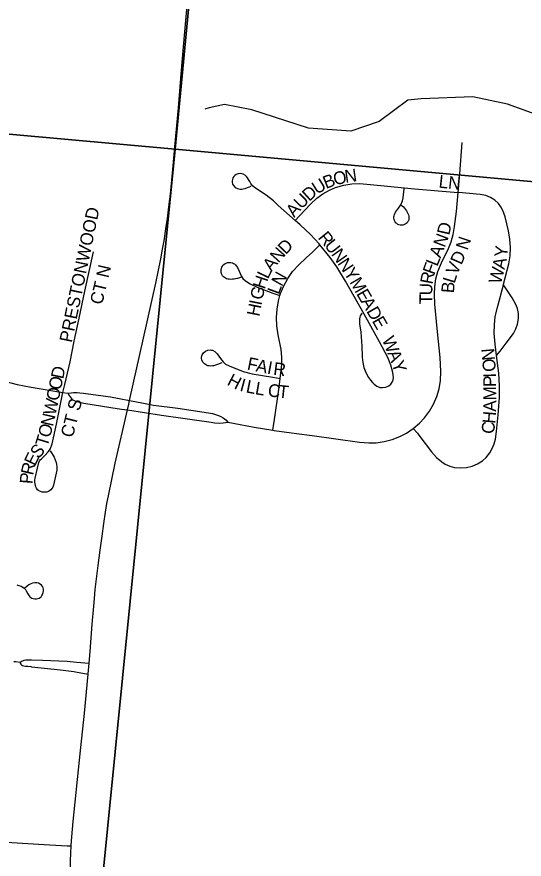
# Model space of a CAD drawing. Extents: x 1410790 to 1770854, y 448063 to 770588.
# Drawn here: x 1549100 to 1551087, y 630526 to 633827 of the extents above; entities that cross this region are included whole.
import ezdxf

# ---------------------------------------------------------------- set-up
doc = ezdxf.new("R2010")
doc.units = 0
for name, color, linetype in [('GM_X_County_Road', 7, 'Continuous'), ('GM_X_Minor_River', 7, 'Continuous'), ('GM_X_Section', 7, 'Continuous'), ('GM_X_Township_Road', 7, 'Continuous'), ('GM_X_Township_Subdivision', 7, 'Continuous'), ('GM_X_Township_Subdivision_Text', 7, 'Continuous')]:
    doc.layers.add(name, color=color, linetype=linetype)

msp = doc.modelspace()

# ---------------------------------------------------------------- linework, layer by layer
at = {"layer": 'GM_X_County_Road'}
for points in [[(1549696.4, 633093.2), (1549701, 633131.6), (1549710.2, 633229.5), (1549718.3, 633317.7), (1549732.4, 633471.2), (1549745.3, 633618.3), (1549753, 633709.4), (1549763.1, 633827.4), (1549772.9, 633945.1), (1549776, 633981), (1549788, 634111.7), (1549796.4, 634196.6), (1549816.6, 634395.7), (1549830.4, 634526.2), (1549841.8, 634643.7), (1549842.2, 634647.7)], [(1549653.4, 632827.7), (1549664.2, 632878.9), (1549670.9, 632916), (1549676.8, 632949.8), (1549683.9, 632996.7), (1549689.8, 633037.3), (1549696.4, 633093.2)], [(1549541.1, 632323.1), (1549595.8, 632568.3), (1549644, 632783.6), (1549653.4, 632827.7)], [(1549532.9, 632286.7), (1549537.9, 632308.9), (1549541.1, 632323.1)], [(1549382.6, 631294.1), (1549386.7, 631339.2), (1549395.3, 631446.8), (1549401, 631517.6), (1549403.6, 631547.9), (1549406.6, 631583.1), (1549418.3, 631676.9), (1549425.7, 631736.3), (1549433.5, 631792.3), (1549440, 631841.4), (1549447, 631885.2), (1549452.6, 631919.5), (1549458.3, 631949.9), (1549485.2, 632077.9), (1549532.9, 632286.7)], [(1549378.7, 631251.3), (1549378.8, 631252.4), (1549382.6, 631294.1)], [(1549350.1, 630964), (1549364.1, 631098.3), (1549378.7, 631251.3)], [(1549312.4, 630577.3), (1549312.4, 630578.8), (1549315, 630613.1), (1549320.7, 630673.8), (1549344.8, 630913.1), (1549350.1, 630964)], [(1549327.6, 629859.6), (1549323.7, 629959.9), (1549320.2, 630077.5), (1549315.8, 630208.9), (1549310.7, 630451.7), (1549310.3, 630488.1), (1549309.8, 630519.7), (1549310.7, 630548.8), (1549312.4, 630577.3)]]:
    msp.add_lwpolyline(points, dxfattribs=at)
at = {"layer": 'GM_X_Minor_River'}
msp.add_lwpolyline([(1552366.4, 633601.7), (1552210.9, 633328.1), (1552100.1, 633298.3), (1551627.5, 633420.2), (1551377.3, 633437.4), (1551210.5, 633416.8), (1551021.5, 633484.8), (1550885.8, 633513.6), (1550683.2, 633505.8), (1550631, 633500.8), (1550519.1, 633416.9), (1550408.1, 633379.1), (1550241.9, 633390.6), (1550020.9, 633463.2), (1549913.1, 633483.5), (1549852.7, 633470.7), (1549836.5, 633465)], dxfattribs=at)
at = {"layer": 'GM_X_Section'}
for points in [[(1550230.3, 638666.5), (1549719.6, 633308.3), (1544399.7, 633789.9), (1544904.4, 639125.6)], [(1550230.3, 638666.5), (1555538.6, 638162.6), (1555022.2, 632826.4), (1549719.6, 633308.3)], [(1544399.7, 633789.9), (1549719.6, 633308.3), (1549189.3, 627980.4), (1543911.7, 628488)], [(1549719.6, 633308.3), (1555022.2, 632826.4), (1554631.8, 628627.9), (1554620.8, 627934.3), (1554618.6, 627918.3), (1554618, 627882.4), (1554617.3, 627836.4), (1554614.8, 627806.4), (1554624.4, 627780.3), (1554668.6, 627671.6), (1554687.9, 627625.3), (1554689.4, 627591.3), (1554684.9, 627563.4), (1554674.5, 627535.6), (1554652.2, 627519.9), (1554620, 627502.5), (1554585.9, 627497), (1554498, 627498.4), (1554418, 627499.6), (1554372, 627500.4), (1554330.2, 627507), (1554298.4, 627519.5), (1554266.6, 627536), (1549189.3, 627980.4)]]:
    msp.add_lwpolyline(points, close=True, dxfattribs=at)
at = {"layer": 'GM_X_Township_Road'}
msp.add_lwpolyline([(1548610.9, 630629.1), (1548648.1, 630625.6), (1548865.9, 630605.1), (1548992.9, 630596.1), (1549079.3, 630590.8), (1549183.8, 630584.4), (1549297.3, 630578.1), (1549312.4, 630577.3)], dxfattribs=at)
at = {"layer": 'GM_X_Township_Subdivision'}
for points in [[(1550828.3, 633139.2), (1550833.4, 633197.5), (1550834.7, 633211.4), (1550844.7, 633334.5)], [(1550189.7, 633029.2), (1550123.7, 633087.8), (1550104.6, 633105.6), (1550076.6, 633128.3), (1550030.1, 633159), (1550020.8, 633168), (1550015.8, 633174.3), (1550011.9, 633181.7), (1550007.6, 633190.1), (1550003.8, 633196.1), (1550000, 633201.2), (1549994.9, 633205.5), (1549986.4, 633210.5), (1549977, 633213), (1549967.3, 633212.4), (1549963.1, 633210.9), (1549958.4, 633209), (1549954, 633205.5), (1549949.9, 633201.6), (1549946.4, 633196.2), (1549944.2, 633189.3), (1549943.6, 633184.2), (1549943.6, 633179), (1549945.1, 633171.4), (1549948.4, 633165.6), (1549955.1, 633158.5), (1549963.8, 633153.9), (1549973.5, 633152.2), (1549980.5, 633152), (1549986.7, 633153), (1549994.6, 633154.9), (1550003.8, 633158.2), (1550011.7, 633161.4), (1550018.2, 633164.1)], [(1550189.7, 633029.2), (1550205.8, 633046.2), (1550250.9, 633093.9), (1550274.9, 633116.4), (1550298.7, 633133.7), (1550324.4, 633148.3), (1550348.7, 633158.2), (1550380.2, 633167.2), (1550412.6, 633172.5), (1550442, 633173.6), (1550484.6, 633170.7), (1550618.2, 633157.5)], [(1550606, 633088.9), (1550609.9, 633086.1), (1550613.9, 633082.6), (1550617.9, 633077.9), (1550622.4, 633072), (1550626.1, 633066.9), (1550629.4, 633062.1), (1550631.8, 633057), (1550633.9, 633051.6), (1550635.2, 633046.5), (1550635.4, 633043), (1550635.7, 633038.5), (1550635, 633033.1), (1550633.6, 633028.2), (1550631.8, 633024.6), (1550628.4, 633020.2), (1550624.6, 633016.7), (1550620.8, 633014.1), (1550616, 633012), (1550611.4, 633010.9), (1550606.2, 633010.4), (1550601.5, 633010.8), (1550596.5, 633012.1), (1550591.9, 633013.9), (1550587.8, 633016.7), (1550583.7, 633020.4), (1550581.2, 633024), (1550578.8, 633028.4), (1550577.5, 633033), (1550576.9, 633038), (1550576.8, 633042.8), (1550577.6, 633047.9), (1550578.9, 633052.4), (1550583.2, 633061.3), (1550595.2, 633077.2), (1550604.5, 633090.7), (1550610.9, 633105.9), (1550613.2, 633117.2), (1550617.6, 633153), (1550618.2, 633157.5)], [(1550618.2, 633157.5), (1550657.6, 633153.5), (1550828.3, 633139.2)], [(1550652.4, 632214), (1550676.8, 632234.8), (1550696.7, 632255.8), (1550716, 632281.5), (1550732.1, 632309.4), (1550744.9, 632338.9), (1550753.8, 632369.7), (1550759, 632401.5), (1550760.7, 632436.9), (1550757.9, 632492.1), (1550748.1, 632593.1), (1550737.6, 632701), (1550735.8, 632740.6), (1550737.2, 632770.5), (1550741.6, 632800.1), (1550749.4, 632829.1), (1550762.9, 632863), (1550790.5, 632918.7), (1550800.7, 632945.8), (1550808.7, 632973.7), (1550814.8, 633005.4), (1550821.7, 633063.7), (1550828.3, 633139.2)], [(1551006.2, 632777.3), (1551006.7, 632779.2), (1551027, 632858.6), (1551032.1, 632890.9), (1551033.5, 632923.7), (1551031.3, 632956.3), (1551025.8, 632988.7), (1551012.4, 633042.8), (1551003.9, 633067.7), (1550996.4, 633082.2), (1550986.7, 633095.3), (1550972.5, 633108.9), (1550956, 633119.4), (1550937.7, 633126.6), (1550915.2, 633131.4), (1550831.3, 633138.9), (1550828.3, 633139.2)], [(1550287.3, 632933), (1550283.6, 632937.4), (1550250.2, 632973.5), (1550209.5, 633011.6), (1550189.7, 633029.2)], [(1550130.3, 632734.4), (1550132.7, 632742.6), (1550144.1, 632769.8), (1550161.4, 632801.5), (1550180, 632828.5), (1550203.8, 632855.7), (1550232.8, 632882.4), (1550257.4, 632905.1), (1550286, 632931.8), (1550287.3, 632933)], [(1550453, 632666.3), (1550449.9, 632663), (1550447.5, 632659.5), (1550445.3, 632655.1), (1550443.3, 632649.8), (1550442.3, 632644.1), (1550442, 632638.6), (1550442.2, 632632), (1550442.7, 632624.2), (1550447.5, 632591.7), (1550451.2, 632536.1), (1550452.5, 632496), (1550453.8, 632480), (1550456, 632466.5), (1550459.5, 632453), (1550464.3, 632440), (1550469.9, 632427.4), (1550477.3, 632413.9), (1550484.7, 632402.6), (1550492.5, 632393.9), (1550499.8, 632387.7), (1550510.3, 632379.9), (1550516.4, 632376.6), (1550522.4, 632375), (1550532.1, 632374), (1550545, 632376), (1550557, 632381.3), (1550564.6, 632387.5), (1550570.6, 632395.3), (1550574.4, 632404.3), (1550575.6, 632414.1), (1550572.6, 632433.5), (1550564.8, 632461.9), (1550553, 632492.5), (1550520.7, 632553.3), (1550460.2, 632662.2), (1550387.5, 632790.6), (1550353.7, 632846.8), (1550327.5, 632884.4), (1550287.3, 632933)], [(1549280.4, 632354.9), (1549287.4, 632385.6), (1549308, 632475.3), (1549324.6, 632555.8), (1549343.7, 632645.6), (1549366.2, 632751.6), (1549400.1, 632906.3)], [(1549978.1, 632806.5), (1549976.4, 632805.9), (1549963.5, 632802.3), (1549956.9, 632800.7), (1549950.5, 632799.7), (1549944.5, 632798.7), (1549937.8, 632798.2), (1549931.4, 632798.6), (1549926.3, 632799.4), (1549921.3, 632800.8), (1549917.2, 632803), (1549913.2, 632805.6), (1549909.4, 632808.4), (1549905.8, 632812.6), (1549903.3, 632817), (1549901.7, 632821.4), (1549900.4, 632825.6), (1549899.8, 632831), (1549900, 632836.3), (1549900.8, 632840.7), (1549902.1, 632845.5), (1549904.7, 632849.7), (1549907.2, 632853.4), (1549911.1, 632857.1), (1549915.5, 632860.3), (1549919.4, 632862.3), (1549924.5, 632864.1), (1549928.9, 632864.8), (1549934.8, 632864.9), (1549938.6, 632864.4), (1549943.9, 632862.9), (1549948.1, 632861.1), (1549951.9, 632858.6), (1549955.7, 632855.3), (1549959.4, 632851.4), (1549963.7, 632845), (1549970.1, 632829.9), (1549977.9, 632811.9), (1549985.4, 632801.3), (1549994.9, 632792.5), (1550014.3, 632780.3), (1550040.7, 632767.4), (1550102.1, 632744.8), (1550130.3, 632734.4)], [(1550979.3, 632499.7), (1550974.1, 632544.5), (1550970, 632586.9), (1550970.5, 632619.7), (1550974.1, 632652.3), (1550983.9, 632693.7), (1551006.2, 632777.3)], [(1550979.3, 632499.7), (1550992.8, 632517.3), (1551016.6, 632548.7), (1551045.2, 632586.6), (1551054.5, 632604), (1551060.8, 632622.7), (1551064.7, 632645.4), (1551064.7, 632665.1), (1551061.1, 632684.5), (1551053.8, 632702.9), (1551040.1, 632725.4), (1551016.4, 632761.7), (1551006.2, 632777.3)], [(1550130.8, 632409.7), (1550137.3, 632464), (1550138.3, 632493.5), (1550135.6, 632522.9), (1550123.5, 632580.8), (1550118, 632616.4), (1550116.6, 632649.2), (1550119, 632681.9), (1550124.4, 632714.3), (1550130.3, 632734.4)], [(1549902.8, 632471.6), (1549885.9, 632464.9), (1549877.5, 632462.4), (1549869.7, 632460), (1549865.7, 632459.1), (1549859.1, 632458.3), (1549852.6, 632458.9), (1549847.8, 632459.9), (1549843.1, 632461.5), (1549834.7, 632466.6), (1549828.2, 632473.9), (1549824.3, 632482.9), (1549823.4, 632487.8), (1549823.5, 632492.6), (1549824.1, 632498), (1549825.6, 632502.8), (1549828, 632506.4), (1549831, 632510.5), (1549838.4, 632516.9), (1549847.3, 632520.9), (1549857, 632522), (1549862.2, 632521.3), (1549866.7, 632520.2), (1549875.4, 632515.8), (1549885, 632506.9), (1549897.4, 632487.6), (1549907.3, 632474.6), (1549917.4, 632466.4), (1549932.1, 632459.1), (1549986.8, 632437.2), (1550021.5, 632427.5), (1550102.3, 632414.4), (1550130.8, 632409.7)], [(1550652.4, 632214), (1550668.7, 632195.4), (1550675.2, 632188), (1550724, 632122.7), (1550744.1, 632100.3), (1550764.2, 632083), (1550778.1, 632074.2), (1550796, 632066.3), (1550814.9, 632061.2), (1550837.8, 632059), (1550860.7, 632060.6), (1550883, 632065.9), (1550904.1, 632074.9), (1550923.4, 632087.3), (1550938.1, 632100.4), (1550952.6, 632118.1), (1550962.5, 632135.1), (1550969.9, 632153.3), (1550974.8, 632172.3), (1550978.6, 632201.6), (1550985.7, 632267), (1550990.1, 632335.6), (1550990.8, 632381.5), (1550987.4, 632430.5), (1550979.3, 632499.7)], [(1548915.4, 632446), (1548933.4, 632437.7), (1548982.6, 632418.5), (1549029.9, 632403.9), (1549100.3, 632386.2), (1549155.3, 632375.7), (1549280.4, 632354.9)], [(1550102.4, 632207.4), (1550106.7, 632233), (1550107.8, 632239.5), (1550126.8, 632376), (1550130.8, 632409.7)], [(1549229.8, 632126.3), (1549235.5, 632118.6), (1549241.8, 632107.5), (1549245.2, 632100.9), (1549249.1, 632090.8), (1549253.1, 632080.8), (1549255.1, 632074), (1549256.3, 632064.1), (1549255.9, 632051), (1549245.7, 632003), (1549243, 631991.8), (1549240.3, 631984.2), (1549236.8, 631977.9), (1549232.4, 631972.8), (1549227.6, 631969.6), (1549223.4, 631966.8), (1549215.6, 631964.3), (1549209.1, 631963.6), (1549199.3, 631964.4), (1549192.4, 631966.3), (1549186, 631969.7), (1549181.1, 631973.5), (1549176.7, 631979.2), (1549173.9, 631984.9), (1549172.2, 631990.1), (1549170.8, 631996.2), (1549170.1, 632002.9), (1549170.3, 632010.6), (1549171.4, 632019.2), (1549180.1, 632057.7), (1549186.3, 632081), (1549188.8, 632086.9), (1549191.4, 632090.8), (1549195.6, 632095.2), (1549209.3, 632107.4), (1549222.7, 632121.7), (1549227.7, 632128.9), (1549231.3, 632135.5), (1549237.8, 632154), (1549255, 632230.6), (1549280.4, 632354.9)], [(1549280.4, 632354.9), (1549299.5, 632352)], [(1549299.5, 632352), (1549312.8, 632353.5), (1549321, 632354.2), (1549329.3, 632354.4), (1549336.3, 632354.3), (1549346.6, 632353.3), (1549360.8, 632351.8), (1549466.1, 632337.3), (1549500.4, 632331.6), (1549541.1, 632323.1)], [(1549299.5, 632352), (1549304.9, 632342.6), (1549308.6, 632337.2), (1549312.1, 632332.5), (1549315.6, 632328.5), (1549319, 632325.6), (1549323.9, 632322.9), (1549330.4, 632320.6), (1549345.8, 632316.9), (1549362.4, 632313.5), (1549467.9, 632296.3), (1549510, 632290.1), (1549532.9, 632286.7)], [(1549541.1, 632323.1), (1549588.8, 632313.9), (1549635.2, 632305.3), (1549729.8, 632292.9), (1549850.1, 632275), (1549866.7, 632272), (1549878.4, 632268.9), (1549889.6, 632265.3), (1549898.9, 632260.7), (1549907.9, 632255.3), (1549918.1, 632247.4), (1549926, 632238.9)], [(1549532.9, 632286.7), (1549666.3, 632265.5), (1549860.9, 632238), (1549874.1, 632236.1), (1549892.1, 632235), (1549908.4, 632236.1), (1549926, 632238.9)], [(1549926, 632238.9), (1549975.1, 632229.3), (1550029.2, 632218.6), (1550102.4, 632207.4)], [(1550256.2, 632186), (1550442.6, 632159.9), (1550478.1, 632157.2), (1550507, 632158.1), (1550538.9, 632162.7), (1550570, 632170.8), (1550600, 632182.4), (1550625.7, 632195.8), (1550652.3, 632213.9), (1550652.4, 632214)], [(1550102.4, 632207.4), (1550107.8, 632206.5), (1550195.5, 632194.4), (1550256.2, 632186)], [(1549099.4, 631600.7), (1549108, 631598.4), (1549116.1, 631595.5), (1549122.5, 631591.9), (1549128.2, 631588.1), (1549133.1, 631583), (1549136.3, 631578), (1549142.9, 631565.1), (1549147.6, 631557.5), (1549150.5, 631554.1), (1549154.1, 631551.4), (1549157.9, 631549), (1549163.7, 631547.1), (1549169.9, 631545.8), (1549176.5, 631546), (1549181.8, 631547), (1549186.8, 631548.7), (1549191.4, 631551.2), (1549194.9, 631554.5), (1549198.1, 631558.7), (1549200.7, 631563.6), (1549203, 631570.5), (1549204, 631577.5), (1549204.1, 631583.4), (1549202.7, 631589.2), (1549200.4, 631594.2), (1549196.6, 631599.4), (1549190.9, 631604.2), (1549184.5, 631607.2), (1549177.3, 631608.6), (1549169.5, 631608.9), (1549161.4, 631608.1), (1549154.1, 631605.4), (1549146.3, 631600.8), (1549139.5, 631596.2), (1549131.4, 631588.4)], [(1549088.2, 631300.8), (1549095.9, 631300), (1549112.5, 631298)], [(1549112.5, 631298), (1549117.8, 631301.2), (1549123, 631303.7), (1549128.9, 631305.8), (1549135, 631306.9), (1549141.7, 631307.4), (1549156.7, 631306.9), (1549199.9, 631305.5), (1549297.3, 631301.4), (1549333, 631298.4), (1549382.6, 631294.1)], [(1549112.5, 631298), (1549113.2, 631294.2), (1549115.3, 631289.7), (1549118.1, 631287), (1549121.3, 631285.1), (1549126.7, 631283.5), (1549133.5, 631282.6), (1549142.6, 631281.5), (1549154, 631280.4), (1549156.5, 631280.1)], [(1549156.5, 631280.1), (1549271, 631268.2), (1549322.9, 631261.5), (1549329.3, 631260.3), (1549378.7, 631251.3)]]:
    msp.add_lwpolyline(points, dxfattribs=at)

# ---------------------------------------------------------------- texts
at = {"layer": 'GM_X_Township_Subdivision_Text'}
for s, rotation, p in [('B', 21.585, (1550310.7, 633152.1)), ('O', 14.2006, (1550345.9, 633166.1)), ('N', 8.0034, (1550387.2, 633176.6)), ('LN', 353.6638, (1550750.5, 633158.1)), ('U', 32.2348, (1550275.7, 633129.7)), ('D', 42.1237, (1550244.9, 633101.6)), ('U', 45.0155, (1550214.3, 633070.9)), ('PRESTONWOOD', 78.2741, (1549314.6, 632548)), ('A', 49.2375, (1550186.2, 633038.3)), ('D', 77.2026, (1550793.7, 632969)), ('R', 309.0126, (1550277.1, 632961.1)), ('N', 69.0224, (1550775.7, 632920.4)), ('D', 46.5456, (1550153, 632892.9)), ('U', 308.6189, (1550302, 632930.4)), ('N', 71.5704, (1550865.2, 632909.8)), ('N', 48.2158, (1550124, 632860.4)), ('N', 305.1997, (1550329, 632896.7)), ('A', 68.6816, (1550759.6, 632879.1)), ('D', 66.1729, (1550841.3, 632852.3)), ('Y', 83.6382, (1551020.2, 632883.1)), ('A', 51.6439, (1550097.2, 632826.5)), ('N', 303.6598, (1550354.1, 632861)), ('L', 68.6957, (1550746.8, 632846.4)), ('A', 77.984, (1551010.2, 632834.8)), ('CT N', 76.865, (1549433.8, 632696.4)), ('Y', 302.4896, (1550378.4, 632824.6)), ('F', 70.3554, (1550735.1, 632813.6)), ('V', 67.407, (1550824.5, 632812)), ('W', 75.7109, (1550995.6, 632777.2)), ('H', 71.7516, (1550070.4, 632757)), ('L', 64.5226, (1550083.6, 632797.2)), ('N', 60.7458, (1550137.5, 632767.4)), ('M', 300.1516, (1550401.7, 632788)), ('R', 79.0044, (1550728.1, 632776.6)), ('L', 72.7747, (1550814.5, 632779.5)), ('U', 88.3166, (1550727, 632734.8)), ('B', 85.4057, (1550811.9, 632742.9)), ('G', 78.6043, (1550062.1, 632715.4)), ('L', 70.0099, (1550126.3, 632736.2)), ('E', 299.8533, (1550428.2, 632742.4)), ('I', 78.6312, (1550057.8, 632693.8)), ('A', 299.8794, (1550445.8, 632711.8)), ('T', 89.6448, (1550726.8, 632699.9)), ('H', 78.6043, (1550049.1, 632650.6)), ('D', 299.8804, (1550467.7, 632673.7)), ('E', 299.8533, (1550489.6, 632635.5)), ('W', 291.8982, (1550529.3, 632562.9)), ('A', 291.9015, (1550550.6, 632509.8)), ('N', 94.9607, (1550973.2, 632482.3)), ('F', 348.3097, (1549999, 632445.2)), ('A', 348.2914, (1550033.4, 632438)), ('Y', 289.4788, (1550566.8, 632469.5)), ('O', 94.3615, (1550976.6, 632437.9)), ('D', 78.1079, (1549280.9, 632405.2)), ('I', 349.5137, (1550077.7, 632428.9)), ('R', 353.0437, (1550102.6, 632424.4)), ('O', 78.1079, (1549271.8, 632362.1)), ('H', 332.5163, (1549919.9, 632386.8)), ('I', 92.0519, (1550977.5, 632413.7)), ('P', 90.0547, (1550977.5, 632376.6)), ('I', 344.7491, (1549969.8, 632362.3)), ('L', 348.7183, (1549994.7, 632355.6)), ('L', 350.4461, (1550030.8, 632348.4)), ('C', 353.0571, (1550081, 632340.2)), ('T', 354.0062, (1550121.2, 632335.3)), ('O', 78.1079, (1549262.7, 632319.1)), ('M', 90.0718, (1550977.6, 632323.8)), ('W', 78.0746, (1549250.9, 632263)), ('CT S', 75.9601, (1549318.9, 632175.4)), ('A', 89.4296, (1550977.2, 632279.2)), ('N', 77.2026, (1549241, 632219.3)), ('H', 85.1958, (1550973.3, 632231.3)), ('O', 75.4673, (1549229.6, 632175.1)), ('C', 83.7939, (1550968.9, 632190.6)), ('T', 72.8338, (1549218.5, 632139.1)), ('S', 48.557, (1549184, 632092.7)), ('E', 64.62, (1549170.9, 632063.9)), ('R', 76.9417, (1549162.9, 632028.1)), ('P', 85.4315, (1549160.4, 631994.9))]:
    msp.add_text(s, height=50, rotation=rotation, dxfattribs=at).set_placement(p)

doc.saveas('drawing.dxf')
